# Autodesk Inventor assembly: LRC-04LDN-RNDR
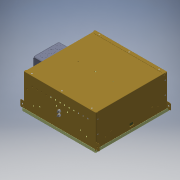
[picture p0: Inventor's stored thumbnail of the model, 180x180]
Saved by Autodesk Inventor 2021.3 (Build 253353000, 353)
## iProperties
load_classification: Lighting
motor: 0 ul
description: 0:0:Regressed Lens 4" Downlight - COB LED
manufacturer: 0:0:The Kirlin Company
model: 0:0:LRC-04LDN
url: 0:0:
Part Number: LRC-04LDN-RNDR
Document SubType Name: Assembly
Designer: JChurch
Author: JChurch
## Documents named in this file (6)
- X:\Revit Files\0000-Un-Zipped\COB\LRC-04LDN-RND\LRC-04LDN-RNDR.iam
- X:\INVENTOR\830\830520-00-00.ipt
- X:\INVENTOR\881\881088-00-00.iam
- X:\INVENTOR\750\750031-00-XX.iam
- X:\INVENTOR\725\725377-00-00.ipt
- X:\Revit Files\0000-Un-Zipped\COB\LRC-04LDN-RND\LRC-04LDN-RNDR_Substitute_1.ipt
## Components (5 placed, 5 different names)
1. 830520-00-00:1 — Mate:1, Mate:2, Mate:3, Mate:4, Tangent:1, Angle:1, Insert:2
2. 881088-00-00:1 [sub-assembly] — Mate:4, Tangent:1, Angle:1
3. 750031-00-XX:1 [sub-assembly] — Insert:1, Insert:2
4. 725377-00-00:1 — Insert:1
5. LRC-04LDN-RNDR_Substitute_1:1
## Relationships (8: Mate 4, Insert 2, Tangent 1, Angle 1)
- Mate:1: 830520-00-00:1
- Mate:2: 830520-00-00:1
- Mate:3: 830520-00-00:1
- Mate:4: 830520-00-00:1 ↔ 881088-00-00:1
- Tangent:1: 830520-00-00:1 ↔ 881088-00-00:1
- Angle:1: 830520-00-00:1 ↔ 881088-00-00:1
- Insert:1: 750031-00-XX:1 ↔ 725377-00-00:1
- Insert:2: 830520-00-00:1 ↔ 750031-00-XX:1
